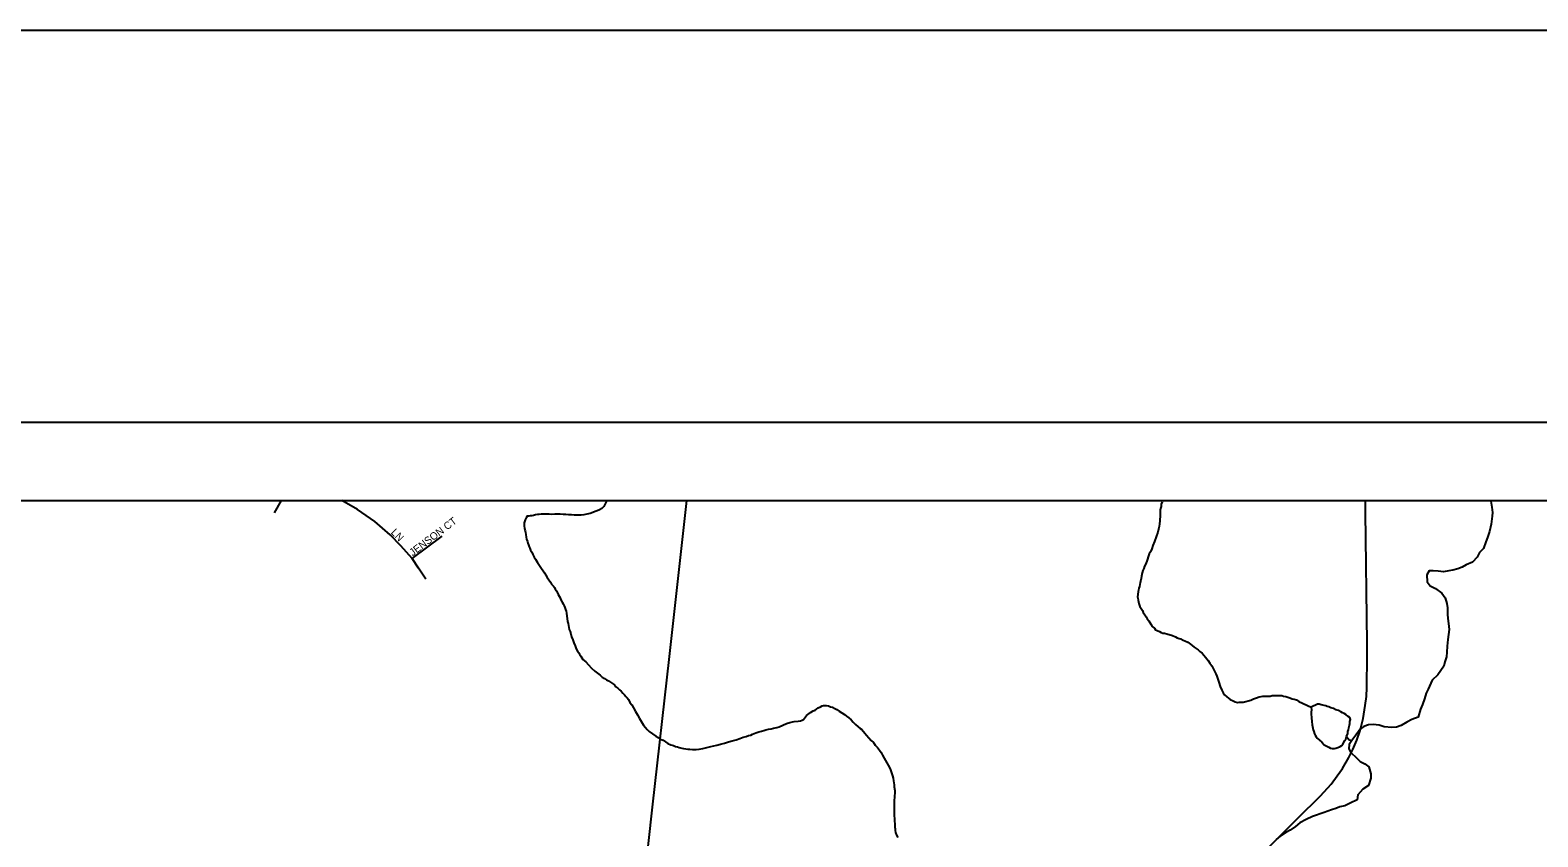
# Model space of a CAD drawing. Extents: x -10.1 to 68, y -9.5 to 29.2.
# Drawn here: x 4.482 to 6.404, y 20.471 to 21.5 of the extents above; entities that cross this region are included whole.
import ezdxf

# ---------------------------------------------------------------- set-up
doc = ezdxf.new("R2010")
doc.units = 0
for name, color, linetype in [('GM_X_Major_Lake', 7, 'Continuous'), ('GM_X_Major_River', 7, 'Continuous'), ('GM_X_Minor_Lake', 7, 'Continuous'), ('GM_X_Minor_River', 7, 'Continuous'), ('GM_X_State_Route', 7, 'Continuous'), ('GM_X_Township_Road', 7, 'Continuous'), ('GM_X_Township_Subdivision', 7, 'Continuous'), ('GM_X_Township_Subdivision_Text', 7, 'Continuous'), ('SH_Border', 7, 'Continuous'), ('SH_Data', 7, 'Continuous')]:
    doc.layers.add(name, color=color, linetype=linetype)

msp = doc.modelspace()

# ---------------------------------------------------------------- linework, layer by layer
at = {"layer": 'GM_X_Major_Lake'}
for points in [[(6.344, 20.9), (6.3443, 20.8994), (6.3458, 20.8918), (6.3466, 20.885), (6.3462, 20.88), (6.3447, 20.8698), (6.3428, 20.8607), (6.3401, 20.853), (6.3382, 20.8473), (6.3352, 20.839), (6.3299, 20.8337), (6.3272, 20.828), (6.3211, 20.8215), (6.3128, 20.8181), (6.3078, 20.815), (6.3022, 20.8131), (6.2961, 20.8112), (6.2908, 20.8104), (6.2839, 20.8093), (6.2771, 20.81), (6.271, 20.8104), (6.2657, 20.8104), (6.2627, 20.8055), (6.2631, 20.7964), (6.2669, 20.7914), (6.2737, 20.788), (6.282, 20.7819), (6.2862, 20.7759), (6.2885, 20.769), (6.2892, 20.7633), (6.2892, 20.755), (6.2896, 20.7497), (6.2904, 20.7432), (6.2911, 20.7356), (6.2896, 20.7227), (6.2889, 20.7143), (6.2885, 20.7067), (6.2881, 20.7007), (6.2858, 20.6942), (6.2847, 20.6889), (6.2767, 20.6778), (6.2695, 20.671), (6.2646, 20.6596), (6.2619, 20.6543), (6.26, 20.6474), (6.2573, 20.6398), (6.2547, 20.6341), (6.2516, 20.6239), (6.2437, 20.6208), (6.2372, 20.6174), (6.23, 20.6132), (6.2243, 20.6109), (6.2183, 20.6105), (6.2084, 20.6117), (6.2019, 20.6136), (6.1944, 20.6143), (6.1883, 20.6139), (6.1826, 20.612), (6.1777, 20.6086), (6.1723, 20.601), (6.167, 20.5941), (6.164, 20.5892), (6.1632, 20.5835), (6.1659, 20.5786), (6.1731, 20.5721), (6.1777, 20.5672), (6.1837, 20.5645), (6.1887, 20.5607), (6.1913, 20.5516), (6.1913, 20.5459), (6.1886, 20.5368)], [(6.1886, 20.5368), (6.1811, 20.5322), (6.175, 20.5246), (6.1738, 20.5185), (6.1651, 20.514), (6.1583, 20.5109), (6.1518, 20.5094), (6.1469, 20.5075), (6.1412, 20.5056), (6.1317, 20.5022), (6.1169, 20.4972), (6.109, 20.4934), (6.101, 20.4892), (6.0953, 20.4843), (6.0885, 20.4797), (6.0832, 20.4766), (6.0756, 20.4721), (6.0706, 20.4679)]]:
    msp.add_lwpolyline(points, dxfattribs=at)
at = {"layer": 'GM_X_Major_River'}
for points in [[(6.344, 20.9), (6.3443, 20.8994), (6.3458, 20.8918), (6.3466, 20.885), (6.3462, 20.88), (6.3447, 20.8698), (6.3428, 20.8607), (6.3401, 20.853), (6.3382, 20.8473), (6.3352, 20.839), (6.3299, 20.8337), (6.3272, 20.828), (6.3211, 20.8215), (6.3128, 20.8181), (6.3078, 20.815), (6.3022, 20.8131), (6.2961, 20.8112), (6.2908, 20.8104), (6.2839, 20.8093), (6.2771, 20.81), (6.271, 20.8104), (6.2657, 20.8104), (6.2627, 20.8055), (6.2631, 20.7964), (6.2669, 20.7914), (6.2737, 20.788), (6.282, 20.7819), (6.2862, 20.7759), (6.2885, 20.769), (6.2892, 20.7633), (6.2892, 20.755), (6.2896, 20.7497), (6.2904, 20.7432), (6.2911, 20.7356), (6.2896, 20.7227), (6.2889, 20.7143), (6.2885, 20.7067), (6.2881, 20.7007), (6.2858, 20.6942), (6.2847, 20.6889), (6.2767, 20.6778), (6.2695, 20.671), (6.2646, 20.6596), (6.2619, 20.6543), (6.26, 20.6474), (6.2573, 20.6398), (6.2547, 20.6341), (6.2516, 20.6239), (6.2437, 20.6208), (6.2372, 20.6174), (6.23, 20.6132), (6.2243, 20.6109), (6.2183, 20.6105), (6.2084, 20.6117), (6.2019, 20.6136), (6.1944, 20.6143), (6.1883, 20.6139), (6.1826, 20.612), (6.1777, 20.6086), (6.1723, 20.601), (6.167, 20.5941), (6.164, 20.5892), (6.1632, 20.5835), (6.1659, 20.5786), (6.1731, 20.5721), (6.1777, 20.5672), (6.1837, 20.5645), (6.1887, 20.5607), (6.1913, 20.5516), (6.1913, 20.5459), (6.1886, 20.5368)], [(6.1886, 20.5368), (6.1811, 20.5322), (6.175, 20.5246), (6.1738, 20.5185), (6.1651, 20.514), (6.1583, 20.5109), (6.1518, 20.5094), (6.1469, 20.5075), (6.1412, 20.5056), (6.1317, 20.5022), (6.1169, 20.4972), (6.109, 20.4934), (6.101, 20.4892), (6.0953, 20.4843), (6.0885, 20.4797), (6.0832, 20.4766), (6.0756, 20.4721), (6.0706, 20.4679)]]:
    msp.add_lwpolyline(points, dxfattribs=at)
at = {"layer": 'GM_X_Minor_Lake'}
for points in [[(6.1581, 20.594), (6.1596, 20.5959), (6.1606, 20.599), (6.1621, 20.6032), (6.162, 20.6055), (6.1631, 20.6078), (6.1634, 20.6101), (6.1641, 20.6135), (6.1648, 20.6158), (6.1648, 20.6185), (6.1655, 20.6208), (6.1647, 20.6234), (6.1627, 20.6249), (6.1597, 20.6271), (6.1573, 20.6286), (6.1554, 20.6293), (6.1531, 20.6308), (6.15, 20.6322), (6.147, 20.6333), (6.1439, 20.6347), (6.1405, 20.6358), (6.1378, 20.6369), (6.1359, 20.6376), (6.1339, 20.6383), (6.1282, 20.6397), (6.1255, 20.6404), (6.1232, 20.6404), (6.1153, 20.6364)], [(6.1153, 20.6364), (6.1158, 20.633), (6.1155, 20.6303), (6.1155, 20.628), (6.1156, 20.6231), (6.1161, 20.6182), (6.1166, 20.614), (6.1174, 20.6098), (6.1179, 20.6076), (6.1187, 20.6057), (6.1195, 20.6027), (6.1203, 20.6008), (6.1215, 20.5989), (6.123, 20.597), (6.1261, 20.5944), (6.1288, 20.5918), (6.132, 20.5885), (6.1346, 20.5874), (6.1377, 20.5856), (6.14, 20.5845), (6.1423, 20.5838), (6.145, 20.5838), (6.1469, 20.5843), (6.1495, 20.5851), (6.1525, 20.5863), (6.1544, 20.5875), (6.1559, 20.5894), (6.1581, 20.594), (6.1596, 20.5959), (6.1606, 20.599), (6.1621, 20.6032), (6.162, 20.6055), (6.1631, 20.6078), (6.1634, 20.6101), (6.1641, 20.6135), (6.1648, 20.6158), (6.1648, 20.6185), (6.1655, 20.6208), (6.1647, 20.6234), (6.1627, 20.6249), (6.1597, 20.6271), (6.1573, 20.6286), (6.1554, 20.6293), (6.1531, 20.6308), (6.15, 20.6322), (6.147, 20.6333), (6.1439, 20.6347), (6.1405, 20.6358), (6.1378, 20.6369), (6.1359, 20.6376), (6.1339, 20.6383), (6.1282, 20.6397), (6.1255, 20.6404), (6.1232, 20.6404), (6.1153, 20.6364)], [(6.1153, 20.6364), (6.1158, 20.633), (6.1155, 20.6303), (6.1155, 20.628), (6.1156, 20.6231), (6.1161, 20.6182), (6.1166, 20.614), (6.1174, 20.6098), (6.1179, 20.6076), (6.1187, 20.6057), (6.1195, 20.6027), (6.1203, 20.6008), (6.1215, 20.5989), (6.123, 20.597), (6.1261, 20.5944), (6.1288, 20.5918), (6.132, 20.5885), (6.1346, 20.5874), (6.1377, 20.5856), (6.14, 20.5845), (6.1423, 20.5838), (6.145, 20.5838), (6.1469, 20.5843), (6.1495, 20.5851), (6.1525, 20.5863), (6.1544, 20.5875), (6.1559, 20.5894), (6.1581, 20.594)]]:
    msp.add_lwpolyline(points, dxfattribs=at)
at = {"layer": 'GM_X_Minor_River'}
for points in [[(5.2173, 20.9), (5.2133, 20.8927), (5.2107, 20.89), (5.208, 20.8884), (5.205, 20.8868), (5.2024, 20.886), (5.1994, 20.8848), (5.196, 20.8836), (5.1918, 20.8827), (5.188, 20.8819), (5.1846, 20.8814), (5.1816, 20.8813), (5.1789, 20.8813), (5.1755, 20.8816), (5.1724, 20.8819), (5.1686, 20.8818), (5.1652, 20.8821), (5.1614, 20.8824), (5.1576, 20.8827), (5.1545, 20.8827), (5.1511, 20.8826), (5.1473, 20.8825), (5.1439, 20.8828), (5.1408, 20.8827), (5.1389, 20.8827), (5.137, 20.8827), (5.1336, 20.8826), (5.1309, 20.8821), (5.1287, 20.8821), (5.1264, 20.8817), (5.1237, 20.8812)], [(5.9259, 20.9), (5.9253, 20.8983), (5.9242, 20.8956), (5.9239, 20.8925), (5.9232, 20.8899)], [(5.1237, 20.8812), (5.1218, 20.8808), (5.1196, 20.8808), (5.1177, 20.8803), (5.1158, 20.8803), (5.1143, 20.878), (5.1132, 20.8753), (5.1118, 20.8718), (5.1119, 20.8677), (5.1123, 20.8643), (5.1131, 20.8616), (5.1136, 20.8593), (5.114, 20.8567), (5.1144, 20.8533), (5.1149, 20.851), (5.1161, 20.848), (5.1165, 20.8457), (5.1173, 20.8435), (5.1181, 20.8412), (5.1189, 20.8393), (5.1201, 20.8367), (5.1217, 20.8341), (5.1229, 20.8314), (5.1245, 20.828), (5.1265, 20.8254), (5.1288, 20.8213), (5.1316, 20.8172), (5.1339, 20.8134), (5.1359, 20.8104), (5.1379, 20.8078), (5.1394, 20.8048), (5.1414, 20.8018), (5.1434, 20.7988), (5.1453, 20.7962), (5.1469, 20.7936), (5.1493, 20.791), (5.1504, 20.7891), (5.1516, 20.7872), (5.1532, 20.785), (5.154, 20.7831), (5.1552, 20.7804), (5.1567, 20.7782), (5.1576, 20.7759), (5.1588, 20.7733), (5.1603, 20.7707), (5.1615, 20.7684), (5.1627, 20.7658), (5.1639, 20.7635), (5.1647, 20.7613), (5.1655, 20.759), (5.166, 20.7563), (5.1673, 20.7457), (5.1678, 20.7431), (5.1682, 20.7408), (5.169, 20.7382), (5.1694, 20.7355), (5.1706, 20.7329), (5.1715, 20.7302), (5.1723, 20.7265), (5.1739, 20.7223), (5.1751, 20.7185), (5.1767, 20.7148), (5.1783, 20.711), (5.1799, 20.708), (5.1815, 20.7061), (5.1823, 20.7043), (5.1842, 20.7016), (5.1866, 20.6975), (5.1905, 20.6942), (5.194, 20.6905), (5.1979, 20.6864), (5.2018, 20.6826), (5.2052, 20.6801), (5.2087, 20.6775), (5.2114, 20.6749), (5.2145, 20.673), (5.2168, 20.6716), (5.2195, 20.6701), (5.2218, 20.6686), (5.2246, 20.6668), (5.2269, 20.6649), (5.2288, 20.6627), (5.2311, 20.6609), (5.2335, 20.6586), (5.2354, 20.6568), (5.2377, 20.6545), (5.2397, 20.6523), (5.2416, 20.6504), (5.2432, 20.6486), (5.2448, 20.6463), (5.2464, 20.6426), (5.2491, 20.6396), (5.2511, 20.6358), (5.2538, 20.6309), (5.2562, 20.6268), (5.259, 20.6223), (5.2614, 20.6178), (5.2641, 20.6137), (5.2664, 20.6107), (5.2688, 20.6081), (5.2711, 20.6055)], [(5.9232, 20.8899), (5.9228, 20.888), (5.9229, 20.8857), (5.9226, 20.8819), (5.9226, 20.8785), (5.9223, 20.8766), (5.9224, 20.8743), (5.9221, 20.8705), (5.9217, 20.867), (5.9207, 20.8636), (5.92, 20.8598), (5.9157, 20.8479), (5.9135, 20.8429), (5.9121, 20.8387), (5.9103, 20.8349), (5.9088, 20.8322), (5.9081, 20.8295), (5.9063, 20.8241), (5.9045, 20.8195), (5.9027, 20.8165), (5.902, 20.8134), (5.9009, 20.8111), (5.8998, 20.808), (5.8995, 20.8057), (5.8991, 20.8035), (5.8984, 20.8008), (5.8981, 20.7985), (5.8974, 20.7954), (5.8967, 20.7931), (5.8964, 20.7905), (5.8957, 20.7882), (5.8953, 20.7859), (5.8946, 20.784), (5.8943, 20.7802), (5.894, 20.7775), (5.8944, 20.7756), (5.8948, 20.773), (5.8957, 20.7688), (5.8969, 20.765), (5.8985, 20.7624), (5.9001, 20.7598), (5.9013, 20.7575), (5.9032, 20.7545), (5.9048, 20.7519), (5.9064, 20.7493), (5.9083, 20.7467), (5.9095, 20.7444), (5.9111, 20.7425), (5.9127, 20.7395), (5.9154, 20.7373), (5.9169, 20.7351), (5.9189, 20.7343), (5.9219, 20.7329), (5.9239, 20.7318), (5.9262, 20.7311), (5.9285, 20.7308), (5.9311, 20.7301), (5.9384, 20.7279), (5.9422, 20.7261), (5.9446, 20.725), (5.9472, 20.7243), (5.9491, 20.7236), (5.9522, 20.7222), (5.9541, 20.7214), (5.958, 20.7196), (5.9615, 20.717), (5.9634, 20.7152), (5.9661, 20.7133), (5.9688, 20.7115), (5.9711, 20.7096), (5.9734, 20.7078), (5.9762, 20.7056), (5.9785, 20.703), (5.9808, 20.7004), (5.984, 20.6962), (5.9863, 20.6929), (5.9887, 20.6895), (5.9903, 20.6857), (5.9922, 20.6824), (5.9938, 20.679), (5.995, 20.676), (5.9963, 20.6722), (5.9975, 20.6684), (5.9995, 20.6631), (6.0015, 20.6582), (6.0031, 20.6549), (6.0047, 20.6522), (6.0078, 20.6496), (6.012, 20.6463), (6.0159, 20.6445), (6.0186, 20.6434), (6.0216, 20.6427), (6.0235, 20.6428), (6.0262, 20.6428), (6.0288, 20.6429), (6.0383, 20.6457), (6.0417, 20.6473), (6.0455, 20.6486), (6.0489, 20.6498), (6.0515, 20.6502), (6.0538, 20.6506)], [(6.0538, 20.6506), (6.0572, 20.6507), (6.0599, 20.6508), (6.0629, 20.6508), (6.0656, 20.6513), (6.0686, 20.6513), (6.0713, 20.6514), (6.0732, 20.6514), (6.0751, 20.6515), (6.0781, 20.6515), (6.08, 20.6508), (6.0831, 20.6501), (6.0854, 20.6494), (6.0881, 20.6483), (6.0911, 20.6473), (6.0938, 20.6466), (6.0965, 20.6459), (6.0996, 20.644), (6.1153, 20.6364)], [(5.2711, 20.6055), (5.2796, 20.5996), (5.2827, 20.5978), (5.2854, 20.5959), (5.2889, 20.5945), (5.2919, 20.5926), (5.295, 20.5904), (5.2989, 20.5886), (5.3023, 20.5875), (5.305, 20.5865), (5.3073, 20.5861), (5.3096, 20.585), (5.3127, 20.5843), (5.3149, 20.584), (5.318, 20.5833), (5.3207, 20.583), (5.3233, 20.5831), (5.3264, 20.5827), (5.331, 20.5825), (5.3351, 20.5829), (5.3397, 20.5838), (5.3446, 20.585), (5.3499, 20.5863), (5.3575, 20.588), (5.3624, 20.5896), (5.3673, 20.5908), (5.3722, 20.5925), (5.3771, 20.5937), (5.382, 20.595), (5.387, 20.5966), (5.3911, 20.5982), (5.3949, 20.5994), (5.3979, 20.6003), (5.4009, 20.6011), (5.4032, 20.6023), (5.4073, 20.6039), (5.4111, 20.6051), (5.4145, 20.6059), (5.4176, 20.6068), (5.4202, 20.6076), (5.4236, 20.6084), (5.427, 20.6089), (5.4297, 20.6097), (5.4319, 20.6101), (5.4342, 20.6105), (5.4368, 20.6117), (5.4417, 20.6137), (5.4463, 20.6157), (5.4504, 20.617), (5.4538, 20.6178), (5.4561, 20.6182), (5.4614, 20.6187), (5.4641, 20.6192), (5.4663, 20.62), (5.4682, 20.6208), (5.4719, 20.6258), (5.4768, 20.6297), (5.4805, 20.6321), (5.4828, 20.6329), (5.4847, 20.6341), (5.4869, 20.6356), (5.4896, 20.6372), (5.4918, 20.6384), (5.4937, 20.6388), (5.4975, 20.6389), (5.4998, 20.6382), (5.5025, 20.6371), (5.5052, 20.6364), (5.5079, 20.635), (5.5106, 20.6335), (5.5133, 20.6316), (5.5171, 20.6295), (5.5202, 20.6272), (5.5229, 20.625), (5.526, 20.6228), (5.5287, 20.6206), (5.5314, 20.6176), (5.5345, 20.6146), (5.5377, 20.6117), (5.5404, 20.6094), (5.5423, 20.608), (5.5462, 20.6035), (5.5485, 20.6009), (5.5513, 20.5975), (5.5544, 20.5942), (5.5571, 20.5916), (5.5595, 20.5882), (5.5622, 20.5852), (5.5649, 20.5818), (5.5669, 20.5788), (5.5689, 20.5755), (5.5708, 20.5717), (5.5776, 20.5597), (5.5791, 20.5567), (5.58, 20.554), (5.5808, 20.5514), (5.5816, 20.5491), (5.5824, 20.5461), (5.5829, 20.5427), (5.5833, 20.5401), (5.5837, 20.5374)], [(6.1606, 20.599), (6.1639, 20.5951), (6.167, 20.5941)], [(5.5837, 20.5374), (5.5838, 20.5348), (5.5843, 20.5302), (5.5844, 20.5268), (5.584, 20.5237), (5.5841, 20.5211), (5.5838, 20.5184), (5.5838, 20.5157), (5.5835, 20.5131), (5.5836, 20.5104), (5.5836, 20.5078), (5.5837, 20.5047), (5.5837, 20.5028), (5.5838, 20.5002), (5.5838, 20.4975), (5.5839, 20.4952), (5.5839, 20.4926), (5.584, 20.4907), (5.5844, 20.4884), (5.5845, 20.4861), (5.5845, 20.4835), (5.5849, 20.4816), (5.585, 20.4793), (5.5854, 20.4766), (5.5866, 20.4732), (5.5882, 20.4702)]]:
    msp.add_lwpolyline(points, dxfattribs=at)
at = {"layer": 'GM_X_State_Route'}
msp.add_lwpolyline([(5.1963, 19.7984), (5.201, 19.8468), (5.2122, 19.9435), (5.2251, 20.0575), (5.2339, 20.137), (5.2458, 20.2452), (5.2563, 20.3354), (5.2755, 20.5089), (5.297, 20.7013), (5.3191, 20.9)], dxfattribs=at)
at = {"layer": 'GM_X_Township_Road'}
msp.add_lwpolyline([(6.0538, 20.4504), (6.059, 20.4557), (6.0982, 20.4949), (6.1271, 20.5235), (6.1408, 20.5384), (6.1486, 20.549), (6.1554, 20.5585), (6.1635, 20.5722), (6.1684, 20.5824), (6.1737, 20.5947), (6.1779, 20.6067), (6.1817, 20.6221), (6.1841, 20.6389), (6.1859, 20.65), (6.1862, 20.6618), (6.1864, 20.672), (6.1867, 20.6916), (6.1867, 20.7183), (6.1848, 20.8848), (6.1846, 20.9)], dxfattribs=at)
at = {"layer": 'GM_X_Township_Subdivision'}
for points in [[(4.7934, 20.8843), (4.8024, 20.9)], [(4.9864, 20.8), (4.9771, 20.8138), (4.969, 20.8262), (4.9545, 20.8424), (4.9412, 20.8562), (4.9214, 20.8735), (4.8995, 20.8885), (4.8795, 20.9), (4.8794, 20.9)], [(4.969, 20.8262), (5.0073, 20.8547)]]:
    msp.add_lwpolyline(points, dxfattribs=at)
at = {"layer": 'SH_Border'}
msp.add_lwpolyline([(1.5, 21.5), (33.5, 21.5), (33.5, 0.5), (1.5, 0.5)], close=True, dxfattribs=at)
at = {"layer": 'SH_Data'}
for p, q in [((2, 21), (9, 21)), ((2.1, 20.9), (8.9, 20.9))]:
    msp.add_line(p, q, dxfattribs=at)

# ---------------------------------------------------------------- texts
at = {"layer": 'GM_X_Township_Subdivision_Text'}
for s, rotation, p in [('JENSON CT', 37.1869, (4.9698, 20.8287)), ('LN', 315, (4.9413, 20.8586))]:
    msp.add_text(s, height=0.00947, rotation=rotation, dxfattribs=at).set_placement(p)

doc.saveas('drawing.dxf')
